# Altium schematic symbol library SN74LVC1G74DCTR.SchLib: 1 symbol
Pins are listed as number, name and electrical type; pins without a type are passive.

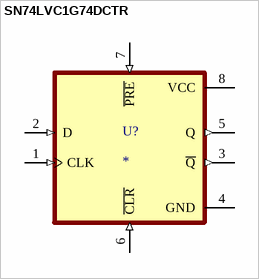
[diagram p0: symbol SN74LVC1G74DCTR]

## SN74LVC1G74DCTR
designator U?
Single Positive-Edge-Triggered D-Type Flip-Flop With Clear and Preset 8-SM8 -40 to 125; MF: Texas Instruments; MP: SN74LVC1G74DCTR
footprint SN74LVC1G74DCTR
pins: 1 CLK (in), 2 D (in), 3 ~{Q} (out), 4 GND (power), 5 Q (out), 6 ~{CLR} (in), 7 ~{PRE} (in), 8 VCC (power)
